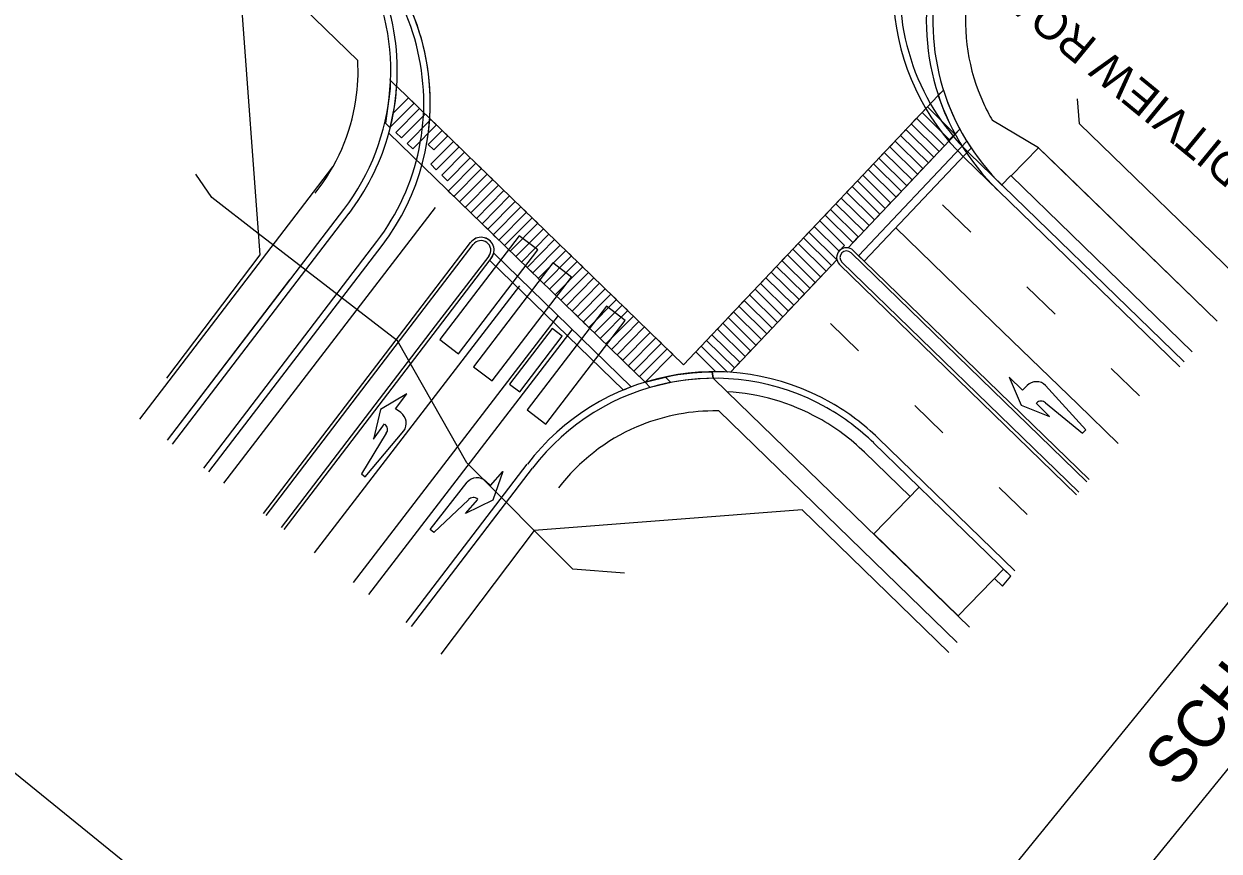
# Model space of a CAD drawing. Extents: x 592613 to 600223, y 4837996 to 4840103.
# Drawn here: x 592951.62 to 592974.48, y 4839229.51 to 4839245.35 of the extents above; entities that cross this region are included whole.
import ezdxf

# ---------------------------------------------------------------- set-up
doc = ezdxf.new("R2010")
doc.units = 0
for name, color, linetype in [('ENG_BORDER', 7, 'Continuous'), ('ENG_BUS-PAD', 7, 'Continuous'), ('ENG_CURB-BACK', 7, 'Continuous'), ('ENG_CURBSTOP', 7, 'Continuous'), ('ENG_EPAVT', 7, 'Continuous'), ('ENG_KILLSTRIP', 7, 'Continuous'), ('ENG_LANEWAY', 7, 'Continuous'), ('ENG_MULTI-TRAIL', 7, 'Continuous'), ('ENG_SH_KILLSTRIP', 7, 'Continuous'), ('ENG_SH_MULTI-TRAIL', 7, 'Continuous'), ('ENG_SH_RIPRAP', 7, 'Continuous'), ('ENG_SIDEWALK', 7, 'Continuous'), ('ENG_TITLEBLOCK', 7, 'Continuous'), ('ENG_TX_TITLEBLOCK', 7, 'Continuous'), ('Level 11', 7, 'Continuous'), ('Level 12', 7, 'Continuous'), ('Level 32', 7, 'Continuous'), ('PMK_LANE', 7, 'Continuous'), ('PMK_LANE_3-6', 7, 'Continuous'), ('ROW_ENG_ROW', 7, 'Continuous')]:
    doc.layers.add(name, color=color, linetype=linetype)

msp = doc.modelspace()

# ---------------------------------------------------------------- linework, layer by layer
at = {"layer": 'ENG_BORDER'}
msp.add_lwpolyline([(592902.303, 4839270.934), (593006.685, 4839186.123)], dxfattribs=at)
at = {"layer": 'ENG_BUS-PAD'}
for p, q in [((592968.748, 4839236.477), (592967.877, 4839235.58)), ((592969.491, 4839234.012), (592967.877, 4839235.58)), ((592970.362, 4839234.909), (592969.491, 4839234.012))]:
    msp.add_line(p, q, dxfattribs=at)
at = {"layer": 'ENG_CURB-BACK'}
for p, q in [((592973.813, 4839238.875), (592969.703, 4839242.868)), ((592954.364, 4839237.374), (592957.739, 4839241.794)), ((592955.06, 4839236.843), (592958.371, 4839241.18)), ((592959.278, 4839239.896), (592960.215, 4839241.123)), ((592959.496, 4839239.564), (592960.517, 4839240.901)), ((592971.956, 4839236.576), (592967.442, 4839240.961)), ((592971.798, 4839236.381), (592967.265, 4839240.784)), ((592956.252, 4839235.933), (592959.278, 4839239.896)), ((592956.55, 4839235.705), (592959.496, 4839239.563)), ((592970.5, 4839234.774), (592967.875, 4839237.324)), ((592959.034, 4839233.809), (592961.349, 4839236.841))]:
    msp.add_line(p, q, dxfattribs=at)
for centre, radius, start, end in [((592954.894, 4839243.835), 4.375, 348.3699, 40.8056), ((592972.751, 4839246.006), 4.375, 169.6205, 225.8289), ((592954.262, 4839244.449), 4.375, 322.6377, 27.9119), ((592973.383, 4839245.392), 4.375, 167.7306, 225.8289), ((592954.894, 4839243.835), 4.375, 322.6377, 348.3699), ((592960.364, 4839241.01), 0.187, 324.4115, 142.9443), ((592967.354, 4839240.873), 0.125, 45.2459, 225.2459), ((592964.827, 4839234.186), 4.375, 60.4988, 142.6377), ((592964.827, 4839234.186), 4.375, 45.8289, 60.4988)]:
    msp.add_arc(centre, radius, start, end, dxfattribs=at)
at = {"layer": 'ENG_CURBSTOP'}
for p, q in [((592969.21, 4839244.077), (592969.111, 4839243.977)), ((592969.525, 4839243.329), (592969.307, 4839243.11)), ((592963.995, 4839238.481), (592963.886, 4839238.587)), ((592964.808, 4839238.561), (592964.786, 4839238.686))]:
    msp.add_line(p, q, dxfattribs=at)
for points in [[(592958.537, 4839243.445), (592958.626, 4839243.358), (592958.708, 4839243.757), (592958.742, 4839244.026), (592958.75, 4839244.147), (592958.75, 4839244.147), (592958.623, 4839244.271), (592958.624, 4839244.284), (592958.624, 4839244.107), (592958.603, 4839243.908)], [(592969.525, 4839243.329), (592969.433, 4839243.237), (592969.317, 4839243.464), (592969.237, 4839243.644), (592969.112, 4839243.978), (592969.21, 4839244.077), (592969.297, 4839243.829), (592969.423, 4839243.532), (592969.466, 4839243.438)], [(592964.808, 4839238.561), (592964.554, 4839238.553), (592964.269, 4839238.526), (592964.026, 4839238.487), (592963.599, 4839238.384), (592963.503, 4839238.486), (592963.997, 4839238.609), (592964.13, 4839238.632), (592964.244, 4839238.648), (592964.41, 4839238.667), (592964.588, 4839238.68), (592964.725, 4839238.685), (592964.786, 4839238.686)]]:
    msp.add_lwpolyline(points, close=True, dxfattribs=at)
at = {"layer": 'ENG_EPAVT'}
for p, q in [((592973.734, 4839238.777), (592969.615, 4839242.779)), ((592954.464, 4839237.298), (592957.839, 4839241.719)), ((592955.159, 4839236.767), (592958.471, 4839241.105)), ((592959.24, 4839239.949), (592960.165, 4839241.161)), ((592971.995, 4839236.625), (592967.486, 4839241.006)), ((592959.533, 4839239.509), (592960.559, 4839240.853)), ((592971.758, 4839236.332), (592967.222, 4839240.739)), ((592956.202, 4839235.971), (592959.239, 4839239.948)), ((592956.6, 4839235.667), (592959.533, 4839239.509)), ((592970.579, 4839234.872), (592967.962, 4839237.414)), ((592958.934, 4839233.885), (592961.25, 4839236.917))]:
    msp.add_line(p, q, dxfattribs=at)
for centre, radius, start, end in [((592954.894, 4839243.835), 4.5, 322.6377, 51.4479), ((592954.894, 4839243.835), 4.5, 349.35, 45.8289), ((592954.262, 4839244.449), 4.5, 343.3725, 33.0068), ((592973.383, 4839245.392), 4.5, 166.783, 225.8289), ((592972.751, 4839246.006), 4.5, 184.2333, 225.8289), ((592954.262, 4839244.449), 4.5, 322.6377, 343.3725), ((592960.364, 4839241.01), 0.25, 321.1016, 142.9443), ((592960.364, 4839241.01), 0.25, 320.9502, 142.7929), ((592967.354, 4839240.873), 0.187, 45.2459, 225.2459), ((592964.827, 4839234.186), 4.5, 60.2342, 142.6377), ((592964.827, 4839234.186), 4.125, 61.0962, 86.5779), ((592964.827, 4839234.186), 4.5, 45.8289, 60.2342), ((592964.827, 4839234.186), 4.125, 45.8289, 61.0962)]:
    msp.add_arc(centre, radius, start, end, dxfattribs=at)
at = {"layer": 'ENG_KILLSTRIP'}
for p, q in [((592973.971, 4839239.07), (592970.509, 4839242.434)), ((592968.573, 4839236.297), (592967.701, 4839237.145)), ((592970.342, 4839234.579), (592970.187, 4839234.729))]:
    msp.add_line(p, q, dxfattribs=at)
at = {"layer": 'ENG_LANEWAY'}
for p, q in [((592955.445, 4839236.553), (592959.495, 4839241.829)), ((592957.18, 4839235.221), (592961.104, 4839240.332)), ((592957.924, 4839234.65), (592961.848, 4839239.761)), ((592958.221, 4839234.422), (592962.109, 4839239.486))]:
    msp.add_line(p, q, dxfattribs=at)
at = {"layer": 'ENG_MULTI-TRAIL'}
for p, q in [((592971.031, 4839242.972), (592970.509, 4839242.434)), ((592974.445, 4839239.656), (592971.031, 4839242.972))]:
    msp.add_line(p, q, dxfattribs=at)
at = {"layer": 'ENG_SH_KILLSTRIP'}
for p, q in [((592970.362, 4839234.909), (592970.187, 4839234.729)), ((592970.187, 4839234.729), (592970.342, 4839234.579)), ((592970.342, 4839234.579), (592970.5, 4839234.774)), ((592970.5, 4839234.774), (592970.362, 4839234.909))]:
    msp.add_line(p, q, dxfattribs=at)
at = {"layer": 'ENG_SH_MULTI-TRAIL'}
msp.add_lwpolyline([(592974.445, 4839239.656), (592971.348, 4839242.664), (592971.031, 4839242.972), (592970.509, 4839242.434), (592970.509, 4839242.434), (592973.971, 4839239.07)], dxfattribs=at)
at = {"layer": 'ENG_SH_RIPRAP'}
msp.add_lwpolyline([(592963.108, 4839234.833), (592962.121, 4839234.906), (592960.09, 4839236.942), (592958.768, 4839239.275), (592956.104, 4839241.332), (592955.214, 4839242.024), (592954.906, 4839242.467)], dxfattribs=at)
at = {"layer": 'ENG_SIDEWALK'}
for p, q in [((592958.007, 4839244.645), (592952.184, 4839250.302)), ((592971.031, 4839242.972), (592970.146, 4839243.499)), ((592957.158, 4839242.123), (592957.531, 4839242.612)), ((592970.5, 4839242.443), (592970.319, 4839242.26)), ((592953.838, 4839237.776), (592957.158, 4839242.123)), ((592954.364, 4839237.374), (592956.709, 4839240.445)), ((592965.073, 4839238.304), (592964.808, 4839238.561)), ((592969.711, 4839233.798), (592965.073, 4839238.304)), ((592969.474, 4839233.505), (592964.914, 4839237.935)), ((592959.034, 4839233.809), (592960.893, 4839236.244))]:
    msp.add_line(p, q, dxfattribs=at)
for centre, start, end in [((592973.383, 4839245.392), 172.7872, 204.683), ((592954.262, 4839244.449), 351.4856, 2.9955), ((592954.262, 4839244.449), 321.332, 351.4856), ((592973.383, 4839245.392), 204.683, 210.3244), ((592964.827, 4839234.186), 90.4558, 113.33), ((592964.827, 4839234.186), 88.6623, 90.4558), ((592964.827, 4839234.186), 113.33, 142.6377)]:
    msp.add_arc(centre, 3.75, start, end, dxfattribs=at)
at = {"layer": 'ENG_TITLEBLOCK'}
for p, q in [((592963.831, 4839220.942), (592991.37, 4839254.837)), ((592965.387, 4839219.678), (592992.927, 4839253.572))]:
    msp.add_line(p, q, dxfattribs=at)
at = {"layer": 'Level 11'}
for p, q in [((592961.093, 4839241.291), (592959.574, 4839239.305)), ((592961.45, 4839241.018), (592961.093, 4839241.291)), ((592959.931, 4839239.032), (592961.45, 4839241.018)), ((592961.738, 4839240.769), (592960.219, 4839238.783)), ((592962.096, 4839240.496), (592961.738, 4839240.769)), ((592960.577, 4839238.51), (592962.096, 4839240.496)), ((592962.763, 4839239.941), (592961.244, 4839237.955)), ((592963.121, 4839239.667), (592962.763, 4839239.941)), ((592961.726, 4839239.511), (592960.912, 4839238.447)), ((592961.602, 4839237.682), (592963.121, 4839239.667)), ((592961.917, 4839239.364), (592961.726, 4839239.511)), ((592959.574, 4839239.305), (592959.931, 4839239.032)), ((592961.104, 4839238.301), (592961.917, 4839239.364)), ((592960.219, 4839238.783), (592960.577, 4839238.51)), ((592960.912, 4839238.447), (592961.104, 4839238.301)), ((592961.244, 4839237.955), (592961.602, 4839237.682))]:
    msp.add_line(p, q, dxfattribs=at)
at = {"layer": 'Level 12'}
for p, q in [((592970.725, 4839238.331), (592970.467, 4839238.58)), ((592970.467, 4839238.58), (592970.698, 4839238.045)), ((592970.811, 4839238.42), (592970.725, 4839238.331)), ((592971.934, 4839237.577), (592971.165, 4839238.425)), ((592958.942, 4839238.266), (592958.444, 4839237.964)), ((592958.73, 4839237.976), (592958.942, 4839238.266)), ((592958.444, 4839237.964), (592958.308, 4839237.397)), ((592958.83, 4839237.903), (592958.73, 4839237.976)), ((592970.698, 4839238.045), (592971.24, 4839237.832)), ((592971.24, 4839237.832), (592970.983, 4839238.082)), ((592971.164, 4839238.09), (592971.87, 4839237.511)), ((592958.308, 4839237.397), (592958.519, 4839237.687)), ((592958.552, 4839237.508), (592958.077, 4839236.729)), ((592958.15, 4839236.675), (592958.885, 4839237.554)), ((592971.87, 4839237.511), (592971.934, 4839237.577)), ((592960.545, 4839236.509), (592960.784, 4839236.777)), ((592960.784, 4839236.777), (592960.593, 4839236.226)), ((592958.077, 4839236.729), (592958.15, 4839236.675)), ((592959.394, 4839235.669), (592960.1, 4839236.572)), ((592960.453, 4839236.592), (592960.545, 4839236.509)), ((592960.125, 4839236.237), (592959.463, 4839235.608)), ((592960.068, 4839235.975), (592960.306, 4839236.242)), ((592960.593, 4839236.226), (592960.068, 4839235.975)), ((592959.463, 4839235.608), (592959.394, 4839235.669))]:
    msp.add_line(p, q, dxfattribs=at)
for centre, radius, start, end in [((592970.991, 4839238.246), 0.25, 45.9051, 135.9273), ((592971.078, 4839238), 0.125, 45.8987, 135.9224), ((592958.683, 4839237.701), 0.25, 323.8506, 53.8728), ((592958.451, 4839237.581), 0.125, 323.8443, 53.8679), ((592960.286, 4839236.405), 0.25, 48.242, 138.2642), ((592960.218, 4839236.154), 0.125, 48.2469, 138.2706)]:
    msp.add_arc(centre, radius, start, end, dxfattribs=at)
at = {"layer": 'PMK_LANE'}
for p, q in [((592958.752, 4839244.149), (592964.239, 4839238.82)), ((592958.974, 4839243.933), (592958.69, 4839243.645)), ((592959.082, 4839243.829), (592958.974, 4839243.933)), ((592964.239, 4839238.82), (592969.111, 4839243.977)), ((592958.631, 4839243.373), (592959.082, 4839243.829)), ((592959.189, 4839243.724), (592958.737, 4839243.266)), ((592958.845, 4839243.162), (592959.297, 4839243.62)), ((592959.297, 4839243.62), (592959.189, 4839243.724)), ((592968.904, 4839243.757), (592968.801, 4839243.648)), ((592968.801, 4839243.648), (592969.334, 4839243.121)), ((592969.437, 4839243.23), (592968.904, 4839243.757)), ((592959.404, 4839243.515), (592958.951, 4839243.056)), ((592959.058, 4839242.951), (592959.512, 4839243.411)), ((592959.512, 4839243.411), (592959.404, 4839243.515)), ((592968.697, 4839243.539), (592968.594, 4839243.43)), ((592968.594, 4839243.43), (592969.128, 4839242.903)), ((592969.231, 4839243.012), (592968.697, 4839243.539)), ((592958.6, 4839243.251), (592963.505, 4839238.488)), ((592958.737, 4839243.266), (592958.845, 4839243.162)), ((592959.62, 4839243.306), (592959.356, 4839243.039)), ((592959.464, 4839242.935), (592959.727, 4839243.202)), ((592959.727, 4839243.202), (592959.62, 4839243.306)), ((592967.385, 4839241.058), (592969.437, 4839243.23)), ((592968.491, 4839243.321), (592968.388, 4839243.212)), ((592968.388, 4839243.212), (592968.922, 4839242.684)), ((592969.025, 4839242.794), (592968.491, 4839243.321)), ((592969.334, 4839243.121), (592969.437, 4839243.23)), ((592958.951, 4839243.056), (592959.058, 4839242.951)), ((592959.356, 4839243.039), (592959.464, 4839242.935)), ((592959.835, 4839243.097), (592959.401, 4839242.658)), ((592959.509, 4839242.554), (592959.943, 4839242.993)), ((592959.943, 4839242.993), (592959.835, 4839243.097)), ((592967.587, 4839240.908), (592969.657, 4839243.099)), ((592967.694, 4839240.803), (592969.741, 4839242.969)), ((592968.285, 4839243.103), (592968.182, 4839242.994)), ((592968.182, 4839242.994), (592968.716, 4839242.466)), ((592968.819, 4839242.575), (592968.285, 4839243.103)), ((592969.128, 4839242.903), (592969.231, 4839243.012)), ((592960.05, 4839242.888), (592959.615, 4839242.448)), ((592959.723, 4839242.343), (592960.158, 4839242.784)), ((592960.158, 4839242.784), (592960.05, 4839242.888)), ((592968.079, 4839242.885), (592967.976, 4839242.776)), ((592967.976, 4839242.776), (592968.509, 4839242.248)), ((592968.613, 4839242.357), (592968.079, 4839242.885)), ((592968.922, 4839242.684), (592969.025, 4839242.794)), ((592959.401, 4839242.658), (592959.509, 4839242.554)), ((592960.265, 4839242.679), (592959.738, 4839242.146)), ((592959.846, 4839242.041), (592960.373, 4839242.575)), ((592960.481, 4839242.47), (592959.954, 4839241.937)), ((592960.373, 4839242.575), (592960.265, 4839242.679)), ((592960.588, 4839242.366), (592960.481, 4839242.47)), ((592967.873, 4839242.667), (592967.77, 4839242.558)), ((592967.77, 4839242.558), (592968.303, 4839242.03)), ((592968.406, 4839242.139), (592967.873, 4839242.667)), ((592968.716, 4839242.466), (592968.819, 4839242.575)), ((592959.615, 4839242.448), (592959.723, 4839242.343)), ((592960.061, 4839241.832), (592960.588, 4839242.366)), ((592960.696, 4839242.261), (592960.169, 4839241.728)), ((592960.803, 4839242.157), (592960.696, 4839242.261)), ((592967.667, 4839242.449), (592967.564, 4839242.34)), ((592967.564, 4839242.34), (592968.097, 4839241.812)), ((592968.2, 4839241.921), (592967.667, 4839242.449)), ((592968.509, 4839242.248), (592968.613, 4839242.357)), ((592959.738, 4839242.146), (592959.846, 4839242.041)), ((592960.276, 4839241.623), (592960.803, 4839242.157)), ((592960.911, 4839242.052), (592960.384, 4839241.519)), ((592961.019, 4839241.948), (592960.911, 4839242.052)), ((592967.255, 4839242.012), (592967.152, 4839241.903)), ((592967.788, 4839241.485), (592967.255, 4839242.012)), ((592967.461, 4839242.231), (592967.358, 4839242.121)), ((592967.358, 4839242.121), (592967.891, 4839241.594)), ((592967.994, 4839241.703), (592967.461, 4839242.231)), ((592968.303, 4839242.03), (592968.406, 4839242.139)), ((592959.954, 4839241.937), (592960.061, 4839241.832)), ((592960.492, 4839241.414), (592961.019, 4839241.948)), ((592961.126, 4839241.843), (592960.599, 4839241.31)), ((592961.234, 4839241.739), (592961.126, 4839241.843)), ((592967.049, 4839241.794), (592966.946, 4839241.685)), ((592967.582, 4839241.267), (592967.049, 4839241.794)), ((592967.152, 4839241.903), (592967.685, 4839241.376)), ((592968.097, 4839241.812), (592968.2, 4839241.921)), ((592960.169, 4839241.728), (592960.276, 4839241.623)), ((592960.707, 4839241.205), (592961.234, 4839241.739)), ((592961.341, 4839241.634), (592960.814, 4839241.1)), ((592961.449, 4839241.53), (592961.341, 4839241.634)), ((592966.843, 4839241.576), (592966.74, 4839241.467)), ((592967.318, 4839241.106), (592966.843, 4839241.576)), ((592966.946, 4839241.685), (592967.479, 4839241.158)), ((592967.891, 4839241.594), (592967.994, 4839241.703)), ((592960.384, 4839241.519), (592960.492, 4839241.414)), ((592960.922, 4839240.996), (592961.449, 4839241.53)), ((592961.557, 4839241.425), (592961.03, 4839240.891)), ((592961.137, 4839240.787), (592961.664, 4839241.321)), ((592961.664, 4839241.321), (592961.557, 4839241.425)), ((592966.637, 4839241.358), (592966.534, 4839241.249)), ((592967.17, 4839240.83), (592966.637, 4839241.358)), ((592966.74, 4839241.467), (592967.215, 4839240.997)), ((592967.685, 4839241.376), (592967.788, 4839241.485)), ((592970.164, 4839239.631), (592968.299, 4839241.443)), ((592960.599, 4839241.31), (592960.707, 4839241.205)), ((592960.814, 4839241.1), (592960.922, 4839240.996)), ((592961.772, 4839241.216), (592961.245, 4839240.682)), ((592961.353, 4839240.578), (592961.879, 4839241.112)), ((592961.879, 4839241.112), (592961.772, 4839241.216)), ((592966.431, 4839241.14), (592966.328, 4839241.031)), ((592966.964, 4839240.612), (592966.431, 4839241.14)), ((592966.534, 4839241.249), (592967.067, 4839240.721)), ((592967.215, 4839240.997), (592967.318, 4839241.106)), ((592967.479, 4839241.158), (592967.582, 4839241.267)), ((592960.608, 4839240.953), (592963.239, 4839238.397)), ((592961.03, 4839240.891), (592961.137, 4839240.787)), ((592961.987, 4839241.007), (592961.46, 4839240.473)), ((592961.568, 4839240.369), (592962.095, 4839240.903)), ((592962.095, 4839240.903), (592961.987, 4839241.007)), ((592966.224, 4839240.922), (592966.121, 4839240.813)), ((592966.758, 4839240.394), (592966.224, 4839240.922)), ((592966.328, 4839241.031), (592966.861, 4839240.503)), ((592960.532, 4839240.817), (592963.087, 4839238.336)), ((592961.245, 4839240.682), (592961.353, 4839240.578)), ((592962.202, 4839240.798), (592961.675, 4839240.264)), ((592961.783, 4839240.16), (592962.31, 4839240.694)), ((592962.31, 4839240.694), (592962.202, 4839240.798)), ((592965.134, 4839238.676), (592967.171, 4839240.831)), ((592966.018, 4839240.704), (592965.915, 4839240.595)), ((592966.552, 4839240.176), (592966.018, 4839240.704)), ((592966.121, 4839240.813), (592966.655, 4839240.285)), ((592967.067, 4839240.721), (592967.17, 4839240.83)), ((592961.46, 4839240.473), (592961.568, 4839240.369)), ((592962.418, 4839240.589), (592961.891, 4839240.055)), ((592961.998, 4839239.951), (592962.525, 4839240.485)), ((592962.525, 4839240.485), (592962.418, 4839240.589)), ((592965.812, 4839240.486), (592965.709, 4839240.376)), ((592966.346, 4839239.958), (592965.812, 4839240.486)), ((592965.915, 4839240.595), (592966.449, 4839240.067)), ((592966.861, 4839240.503), (592966.964, 4839240.612)), ((592961.675, 4839240.264), (592961.783, 4839240.16)), ((592962.633, 4839240.38), (592962.106, 4839239.846)), ((592962.213, 4839239.742), (592962.74, 4839240.276)), ((592962.74, 4839240.276), (592962.633, 4839240.38)), ((592965.606, 4839240.267), (592965.503, 4839240.158)), ((592966.14, 4839239.74), (592965.606, 4839240.267)), ((592965.709, 4839240.376), (592966.243, 4839239.849)), ((592966.655, 4839240.285), (592966.758, 4839240.394)), ((592961.891, 4839240.055), (592961.998, 4839239.951)), ((592962.848, 4839240.171), (592962.321, 4839239.637)), ((592962.429, 4839239.533), (592962.956, 4839240.067)), ((592963.063, 4839239.962), (592962.536, 4839239.428)), ((592962.956, 4839240.067), (592962.848, 4839240.171)), ((592963.171, 4839239.858), (592963.063, 4839239.962)), ((592965.4, 4839240.049), (592965.297, 4839239.94)), ((592965.933, 4839239.522), (592965.4, 4839240.049)), ((592965.503, 4839240.158), (592966.037, 4839239.631)), ((592966.243, 4839239.849), (592966.346, 4839239.958)), ((592962.106, 4839239.846), (592962.213, 4839239.742)), ((592962.644, 4839239.324), (592963.171, 4839239.858)), ((592963.278, 4839239.753), (592962.751, 4839239.219)), ((592963.386, 4839239.649), (592963.278, 4839239.753)), ((592965.194, 4839239.831), (592965.091, 4839239.722)), ((592965.091, 4839239.722), (592965.624, 4839239.194)), ((592965.727, 4839239.304), (592965.194, 4839239.831)), ((592965.297, 4839239.94), (592965.83, 4839239.413)), ((592966.037, 4839239.631), (592966.14, 4839239.74)), ((592962.321, 4839239.637), (592962.429, 4839239.533)), ((592962.859, 4839239.115), (592963.386, 4839239.649)), ((592963.494, 4839239.544), (592962.967, 4839239.01)), ((592963.601, 4839239.44), (592963.494, 4839239.544)), ((592964.988, 4839239.613), (592964.885, 4839239.504)), ((592964.885, 4839239.504), (592965.418, 4839238.976)), ((592965.521, 4839239.085), (592964.988, 4839239.613)), ((592965.83, 4839239.413), (592965.933, 4839239.522)), ((592971.778, 4839238.063), (592970.164, 4839239.631)), ((592962.536, 4839239.428), (592962.644, 4839239.324)), ((592963.074, 4839238.906), (592963.601, 4839239.44)), ((592963.709, 4839239.335), (592963.182, 4839238.801)), ((592963.816, 4839239.231), (592963.709, 4839239.335)), ((592964.782, 4839239.395), (592964.679, 4839239.286)), ((592964.679, 4839239.286), (592965.212, 4839238.758)), ((592965.315, 4839238.867), (592964.782, 4839239.395)), ((592965.624, 4839239.194), (592965.727, 4839239.304)), ((592962.751, 4839239.219), (592962.859, 4839239.115)), ((592963.29, 4839238.697), (592963.816, 4839239.231)), ((592963.924, 4839239.126), (592963.397, 4839238.592)), ((592964.032, 4839239.022), (592963.924, 4839239.126)), ((592964.576, 4839239.177), (592964.473, 4839239.068)), ((592964.473, 4839239.068), (592964.858, 4839238.686)), ((592965.079, 4839238.679), (592964.576, 4839239.177)), ((592965.418, 4839238.976), (592965.521, 4839239.085)), ((592962.967, 4839239.01), (592963.074, 4839238.906)), ((592963.505, 4839238.488), (592964.032, 4839239.022)), ((592965.212, 4839238.758), (592965.315, 4839238.867)), ((592963.182, 4839238.801), (592963.29, 4839238.697)), ((592963.397, 4839238.592), (592963.505, 4839238.488)), ((592972.551, 4839237.313), (592971.778, 4839238.063))]:
    msp.add_line(p, q, dxfattribs=at)
for points in [[(592969.657, 4839243.099), (592969.741, 4839242.969), (592967.694, 4839240.803), (592967.587, 4839240.908)], [(592960.532, 4839240.817), (592960.608, 4839240.953), (592963.239, 4839238.397), (592963.087, 4839238.336)]]:
    msp.add_lwpolyline(points, close=True, dxfattribs=at)
msp.add_lwpolyline([(592966.449, 4839240.067), (592966.51, 4839240.132), (592966.552, 4839240.176)], dxfattribs=at)
for centre, start, end in [((592954.262, 4839244.449), 346.1571, 349.7059), ((592964.827, 4839234.186), 86.7865, 89.5933)]:
    msp.add_arc(centre, 4.5, start, end, dxfattribs=at)
at = {"layer": 'PMK_LANE_3-6'}
for p, q in [((592969.732, 4839241.358), (592969.194, 4839241.881)), ((592971.346, 4839239.79), (592970.808, 4839240.313)), ((592967.048, 4839239.609), (592967.586, 4839239.087)), ((592972.96, 4839238.222), (592972.422, 4839238.745)), ((592968.662, 4839238.041), (592969.2, 4839237.519)), ((592970.276, 4839236.473), (592970.814, 4839235.951))]:
    msp.add_line(p, q, dxfattribs=at)
at = {"layer": 'ROW_ENG_ROW'}
for p, q in [((592955.721, 4839246.518), (592956.135, 4839240.926)), ((592971.811, 4839243.434), (592971.776, 4839243.91)), ((592974.997, 4839240.339), (592971.811, 4839243.434)), ((592956.135, 4839240.926), (592954.35, 4839238.561)), ((592966.506, 4839236.04), (592961.378, 4839235.645)), ((592969.316, 4839233.31), (592966.506, 4839236.04)), ((592961.378, 4839235.645), (592959.593, 4839233.279))]:
    msp.add_line(p, q, dxfattribs=at)

# ---------------------------------------------------------------- texts
at = {"layer": 'ENG_TX_TITLEBLOCK'}
msp.add_text('SCHEMATIC WIRING DIAGRAM', height=0.9, rotation=50.9062, dxfattribs=at).set_placement((592973.698, 4839230.689))
at = {"layer": 'Level 32'}
msp.add_text('CREDITVIEW ROAD', height=0.625, rotation=140.5921, dxfattribs=at).set_placement((592976.415, 4839241.537))

doc.saveas('drawing.dxf')
